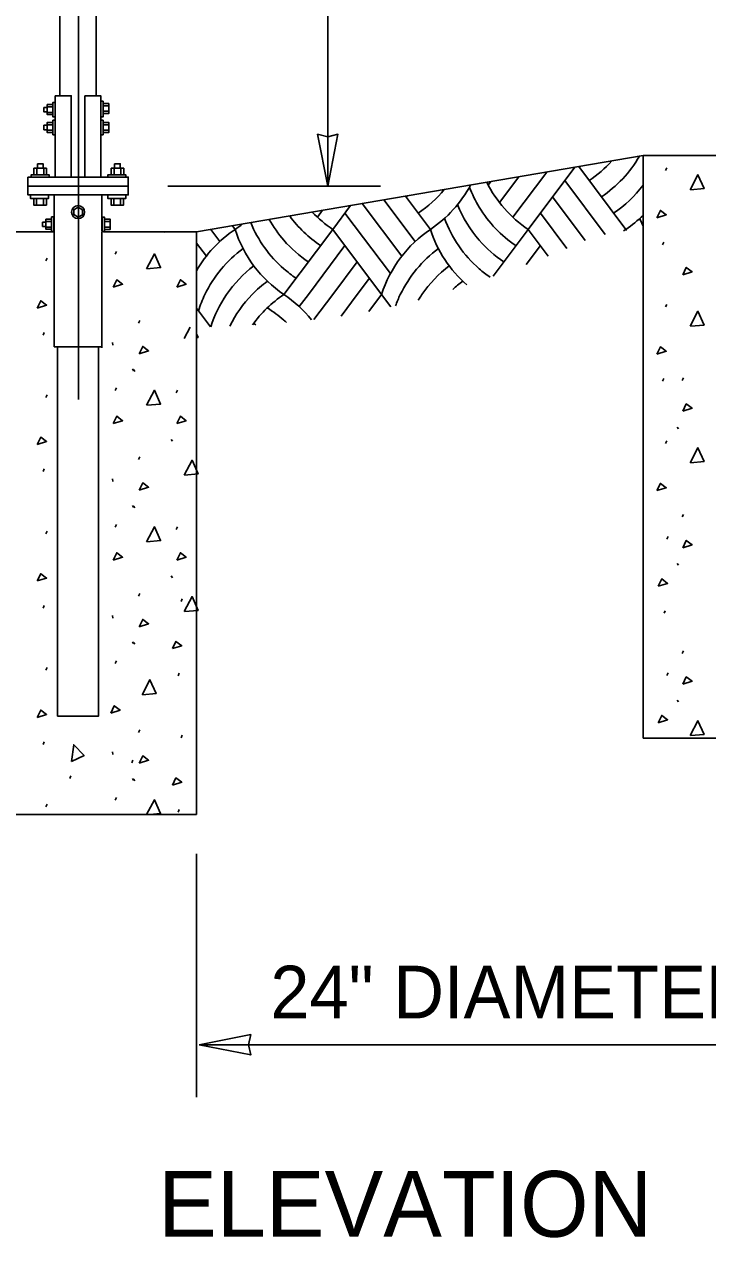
# Model space of a CAD drawing. Extents: x 99862 to 103151, y 99997 to 117076.
# Drawn here: x 101502.3 to 101710.1, y 109727.4 to 110096.3 of the extents above; entities that cross this region are included whole.
import ezdxf

# ---------------------------------------------------------------- set-up
doc = ezdxf.new("R2010")
doc.units = 0
for name, color, linetype in [('Level 15', 7, 'Continuous'), ('Level 2', 7, 'Continuous'), ('Level 20', 7, 'Continuous'), ('Level 5', 7, 'Continuous'), ('Level 6', 7, 'Continuous')]:
    doc.layers.add(name, color=color, linetype=linetype)

msp = doc.modelspace()

# ---------------------------------------------------------------- linework, layer by layer
at = {"layer": 'Level 15'}
for p, q in [((101518.83, 109982.23), (101518.83, 110894.27)), ((101594.55, 110047.07), (101594.55, 110786.06)), ((101610.55, 110047.07), (101545.9, 110047.07)), ((101554.66, 109844.1), (101554.66, 109770.1)), ((101555.43, 109786.1), (101801.61, 109786.1))]:
    msp.add_line(p, q, dxfattribs=at)
for points in [[(101594.55, 110047.07), (101591.46, 110062.8), (101594.55, 110062.07), (101597.63, 110062.8)], [(101555.43, 109786.1), (101571.15, 109783.01), (101570.42, 109786.1), (101571.15, 109789.18)]]:
    msp.add_lwpolyline(points, close=True, dxfattribs=at)
at = {"layer": 'Level 2'}
for p, q in [((101511.38, 110033.49), (101511.38, 110044.36)), ((101525.92, 110033.49), (101525.92, 110044.36)), ((101511.38, 109998.23), (101511.38, 110033.49)), ((101525.92, 110033.17), (101525.92, 109997.91)), ((101525.92, 109998.23), (101511.38, 109998.23))]:
    msp.add_line(p, q, dxfattribs=at)
for points in [[(101513.12, 110074.51), (101513.12, 110394.09), (101524.2, 110394.09), (101524.2, 110074.43)], [(101509.31, 110071.16), (101511.04, 110071.16)], [(101509.31, 110069.46), (101511.04, 110069.46)], [(101528.01, 110071.5), (101526.28, 110071.5)], [(101528.01, 110069.8), (101526.28, 110069.8)], [(101509.31, 110065.73), (101511.04, 110065.73)], [(101528.01, 110065.73), (101526.28, 110065.73)], [(101509.31, 110064.03), (101511.04, 110064.03)], [(101528.01, 110064.03), (101526.28, 110064.03)], [(101506.14, 110052.49), (101506.14, 110050.46)], [(101508.21, 110052.49), (101508.21, 110050.46)], [(101529.63, 110052.49), (101529.63, 110050.46)], [(101531.71, 110052.49), (101531.71, 110050.46)], [(101506.03, 110041.31), (101506.03, 110043.34)], [(101508.11, 110041.31), (101508.11, 110043.34)], [(101529.52, 110041.31), (101529.52, 110043.34)], [(101531.6, 110041.31), (101531.6, 110043.34)], [(101508.9, 110036.32), (101510.63, 110036.32)], [(101528.42, 110036.3), (101526.69, 110036.3)], [(101508.9, 110034.62), (101510.63, 110034.62)], [(101528.42, 110034.6), (101526.69, 110034.6)], [(101524.89, 109998.23), (101524.89, 109885.99), (101512.42, 109885.99), (101512.42, 109998.32)]]:
    msp.add_lwpolyline(points, dxfattribs=at)
for points in [[(101511.73, 110072.51), (101511.73, 110068.1), (101511.04, 110068.1), (101511.04, 110072.51)], [(101511.73, 110074.55), (101516.58, 110074.55), (101516.58, 110049.79), (101511.73, 110049.79)], [(101520.74, 110074.55), (101525.58, 110074.55), (101525.58, 110049.79), (101520.74, 110049.79)], [(101525.58, 110072.85), (101526.28, 110072.85), (101526.28, 110068.1), (101525.58, 110068.1)], [(101508.27, 110070.99), (101509.31, 110070.99), (101509.31, 110069.63), (101508.27, 110069.63)], [(101511.04, 110071.83), (101511.04, 110068.78), (101509.31, 110068.78), (101509.31, 110071.83)], [(101526.28, 110072.17), (101528.01, 110072.17), (101528.01, 110069.12), (101526.28, 110069.12)], [(101508.27, 110065.56), (101509.31, 110065.56), (101509.31, 110064.2), (101508.27, 110064.2)], [(101511.04, 110066.41), (101511.04, 110063.35), (101509.31, 110063.35), (101509.31, 110066.41)], [(101511.73, 110067.09), (101511.73, 110062.68), (101511.04, 110062.68), (101511.04, 110067.09)], [(101525.58, 110067.09), (101526.28, 110067.09), (101526.28, 110062.68), (101525.58, 110062.68)], [(101526.28, 110066.41), (101528.01, 110066.41), (101528.01, 110063.35), (101526.28, 110063.35)], [(101504.37, 110049.78), (101504.37, 110050.46), (101509.91, 110050.46), (101509.91, 110049.78)], [(101505.24, 110050.46), (101505.24, 110052.49), (101509.05, 110052.49), (101509.05, 110050.46)], [(101506.28, 110053.85), (101508.01, 110053.85), (101508.01, 110052.49), (101506.28, 110052.49)], [(101527.69, 110049.78), (101527.69, 110050.46), (101533.23, 110050.46), (101533.23, 110049.78)], [(101528.73, 110050.46), (101528.73, 110052.49), (101532.54, 110052.49), (101532.54, 110050.46)], [(101529.77, 110053.85), (101531.5, 110053.85), (101531.5, 110052.49), (101529.77, 110052.49)], [(101503.42, 110049.79), (101533.9, 110049.79), (101533.9, 110047.07), (101503.42, 110047.07)], [(101503.42, 110047.07), (101533.9, 110047.07), (101533.9, 110044.36), (101503.42, 110044.36)], [(101504.17, 110044.36), (101509.71, 110044.36), (101509.71, 110043.34), (101504.17, 110043.34)], [(101505.21, 110043.34), (101509.02, 110043.34), (101509.02, 110041.31), (101505.21, 110041.31)], [(101527.66, 110044.36), (101533.2, 110044.36), (101533.2, 110043.34), (101527.66, 110043.34)], [(101528.7, 110043.34), (101532.51, 110043.34), (101532.51, 110041.31), (101528.7, 110041.31)], [(101520.01, 110039.88), (101518.72, 110040.64), (101517.41, 110039.9), (101517.4, 110038.4), (101518.69, 110037.64), (101520, 110038.38)], [(101507.86, 110036.15), (101508.9, 110036.15), (101508.9, 110034.79), (101507.86, 110034.79)], [(101510.63, 110037), (101510.63, 110033.95), (101508.9, 110033.95), (101508.9, 110037)], [(101511.32, 110037.68), (101511.32, 110033.27), (101510.63, 110033.27), (101510.63, 110037.68)], [(101526, 110037.66), (101526.69, 110037.66), (101526.69, 110033.25), (101526, 110033.25)], [(101526.69, 110036.98), (101528.42, 110036.98), (101528.42, 110033.92), (101526.69, 110033.92)]]:
    msp.add_lwpolyline(points, close=True, dxfattribs=at)
msp.add_circle((101518.67, 110039.17), 1.98, dxfattribs=at)
at = {"layer": 'Level 5'}
for p, q in [((101554.66, 110033.17), (101690.42, 110056.32)), ((101650.83, 110037.61), (101661.12, 110051.33)), ((101655.49, 110033.92), (101669.63, 110052.78)), ((101670.88, 110052.99), (101685.18, 110033.92)), ((101643.31, 110047.39), (101644.09, 110048.42)), ((101646.75, 110042.08), (101652.6, 110049.87)), ((101666.62, 110048.77), (101678.92, 110032.37)), ((101618.22, 110044.01), (101625.79, 110033.92)), ((101662.91, 110043.82), (101672.84, 110030.58)), ((101591.43, 110037.61), (101593.01, 110039.71)), ((101596.09, 110033.92), (101601.52, 110041.16)), ((101605.05, 110041.77), (101617.06, 110025.76)), ((101611.64, 110042.89), (101621.13, 110030.23)), ((101599.8, 110038.87), (101613.61, 110020.45)), ((101659.2, 110038.87), (101667.27, 110028.1)), ((101558.97, 110033.91), (101561.74, 110030.23)), ((101565.56, 110035.03), (101566.39, 110033.92)), ((101581.24, 110014.12), (101596.09, 110033.92)), ((101596.09, 110033.92), (101610.94, 110014.12)), ((101644.81, 110019.69), (101655.49, 110033.92)), ((101655.49, 110033.92), (101661.6, 110025.77)), ((101554.66, 110029.76), (101557.66, 110025.76)), ((101588.66, 110014.12), (101599.8, 110028.97)), ((101654.88, 110023.21), (101659.2, 110028.97)), ((101596.09, 110014.12), (101603.51, 110024.02)), ((101603.51, 110014.12), (101607.23, 110019.07)), ((101585.89, 110010.43), (101588.66, 110014.12)), ((101590.38, 110006.51), (101596.09, 110014.12)), ((101598.59, 110007.56), (101603.51, 110014.12)), ((101607.08, 110008.98), (101610.94, 110014.12)), ((101610.94, 110014.12), (101613.77, 110010.34)), ((101554.66, 110009.96), (101558.91, 110004.29)), ((101607.23, 110009.17), (101607.34, 110009.02))]:
    msp.add_line(p, q, dxfattribs=at)
for centre, start, end in [((101653.09, 110079.96), 303.9036, 317.7724), ((101656.8, 110075.01), 303.9036, 329.8459), ((101604.83, 110065.11), 303.9036, 331.8449), ((101672.73, 110060.16), 200.8778, 211.332), ((101676.45, 110065.11), 206.713, 236.0964), ((101660.51, 110070.06), 303.9036, 322.7353), ((101597.4, 110075.01), 303.9036, 304.6825), ((101601.11, 110070.06), 303.9036, 320.2298), ((101669.02, 110055.21), 201.4344, 220.9416), ((101672.73, 110060.16), 211.3319, 236.0964), ((101545.43, 110065.11), 303.9036, 308.1444), ((101605.91, 110050.26), 202.3268, 228.9599), ((101609.62, 110055.21), 209.0811, 220.9416), ((101613.34, 110060.16), 216.1301, 236.0964), ((101617.05, 110065.11), 223.6431, 236.0964), ((101665.31, 110050.26), 200.2432, 228.9599), ((101664.22, 110065.11), 303.9036, 314.1913), ((101724.71, 110050.26), 200.2432, 204.1477), ((101578.53, 110016.07), 152.8993, 153.2678), ((101587.35, 110002.73), 123.9036, 150.4555), ((101602.2, 110045.31), 197.6434, 236.0964), ((101646.75, 110002.73), 123.9036, 162.3566), ((101661.6, 110045.31), 197.6434, 228.8095), ((101706.14, 110002.73), 123.9036, 125.2286), ((101720.99, 110045.31), 197.6434, 198.2367), ((101609.62, 110055.21), 220.9415, 236.0964), ((101669.02, 110055.21), 220.9415, 236.0964), ((101591.06, 109997.78), 126.3063, 154.2266), ((101650.46, 109997.78), 126.3063, 154.2266), ((101594.78, 109992.83), 127.1006, 145.4911), ((101605.91, 110050.26), 228.9599, 236.0964), ((101654.17, 109992.83), 127.1006, 145.4911), ((101665.31, 110050.26), 228.9599, 235.28), ((101598.49, 109987.88), 126.331, 135.7128), ((101657.88, 109987.88), 126.331, 132.389), ((101591.06, 109997.78), 154.2265, 162.3566), ((101594.78, 109992.83), 145.491, 162.2427), ((101598.49, 109987.88), 135.7127, 153.7793), ((101602.2, 109982.93), 123.9036, 144.2828), ((101560.28, 109982.93), 38.6821, 56.0963), ((101650.46, 109997.78), 154.2265, 159.9676), ((101654.17, 109992.83), 145.491, 148.6071), ((101556.57, 109977.98), 48.9597, 58.5465), ((101556.57, 109977.98), 47.3973, 48.9597), ((101552.85, 109973.03), 58.0847, 59.3021)]:
    msp.add_arc(centre, 37.58, start, end, dxfattribs=at)
at = {"layer": 'Level 6'}
for p, q in [((101697.25, 110051.8), (101697.61, 110052.6)), ((101554.66, 110033.17), (101526.4, 110033.17)), ((101696.37, 110029.25), (101696.72, 110030.05)), ((101508.91, 110024.34), (101509.27, 110025.14)), ((101529.96, 110026.38), (101530.32, 110027.18)), ((101697.25, 110010.32), (101697.61, 110011.12)), ((101537.07, 110005.43), (101537.42, 110006.23)), ((101508.03, 110001.79), (101508.38, 110002.59)), ((101529.14, 109999.56), (101529.23, 109998.76)), ((101535.2, 109991.49), (101535.56, 109990.95)), ((101535.56, 109991.28), (101535.91, 109990.75)), ((101696.37, 109987.77), (101696.72, 109988.57)), ((101702.3, 109987.97), (101702.66, 109988.77)), ((101529.96, 109984.9), (101530.32, 109985.7)), ((101548.5, 109984.2), (101548.86, 109985)), ((101508.91, 109982.86), (101509.27, 109983.66)), ((101700.79, 109973.82), (101701.15, 109973.29)), ((101547, 109970.05), (101547.35, 109969.52)), ((101697.25, 109968.84), (101697.61, 109969.64)), ((101537.07, 109963.95), (101537.42, 109964.75)), ((101508.03, 109960.31), (101508.38, 109961.1)), ((101529.14, 109958.07), (101529.23, 109957.28)), ((101535.2, 109950), (101535.56, 109949.47)), ((101535.56, 109949.8), (101535.91, 109949.27)), ((101702.3, 109946.49), (101702.66, 109947.28)), ((101529.96, 109943.42), (101530.32, 109944.22)), ((101548.5, 109942.72), (101548.86, 109943.52)), ((101508.91, 109941.38), (101509.27, 109942.18)), ((101697.68, 109939.77), (101698.04, 109940.57)), ((101700.79, 109932.34), (101701.15, 109931.81)), ((101547, 109928.57), (101547.35, 109928.04)), ((101537.07, 109922.46), (101537.42, 109923.26)), ((101549.97, 109920.81), (101550.33, 109921.61)), ((101508.03, 109918.82), (101508.38, 109919.62)), ((101696.8, 109917.22), (101697.15, 109918.01)), ((101529.14, 109916.59), (101529.23, 109915.79)), ((101535.2, 109908.52), (101535.56, 109907.99)), ((101535.56, 109908.32), (101535.91, 109907.79)), ((101702.3, 109905), (101702.66, 109905.8)), ((101508.91, 109899.9), (101509.27, 109900.7)), ((101529.96, 109901.94), (101530.32, 109902.74)), ((101697.68, 109898.29), (101698.04, 109899.09)), ((101549.08, 109898.26), (101549.44, 109899.05)), ((101700.79, 109890.86), (101701.15, 109890.33)), ((101537.07, 109880.98), (101537.42, 109881.78)), ((101508.03, 109877.34), (101508.38, 109878.14)), ((101549.97, 109879.33), (101550.33, 109880.13)), ((101529.14, 109875.11), (101529.23, 109874.31)), ((101534.98, 109871.74), (101535.34, 109872.54)), ((101516.11, 109867.04), (101516.46, 109867.84)), ((101535.2, 109867.04), (101535.56, 109866.51)), ((101535.56, 109866.84), (101535.91, 109866.31)), ((101508.91, 109858.42), (101509.27, 109859.22)), ((101529.96, 109860.46), (101530.32, 109861.26)), ((101549.08, 109856.77), (101549.44, 109857.57))]:
    msp.add_line(p, q, dxfattribs=at)
for points in [[(101719.14, 110056.32), (101690.42, 110056.32), (101690.42, 109879.25)], [(101690.42, 109879.25), (101762.42, 109879.25), (101762.42, 110056.32)], [(101704.7, 110045.97), (101707.1, 110050.49), (101708.96, 110046.32), (101704.79, 110045.97)], [(101694.61, 110037.46), (101695.67, 110039.68), (101697.45, 110038.35), (101694.61, 110037.46)], [(101511.38, 110033.17), (101482.66, 110033.17), (101482.66, 109856.1)], [(101482.66, 109856.1), (101554.66, 109856.1), (101554.66, 110033.17)], [(101539.46, 110021.94), (101541.86, 110026.47), (101543.73, 110022.3), (101539.55, 110021.94)], [(101702.48, 110020.12), (101703.54, 110022.34), (101705.32, 110021.01), (101702.48, 110020.12)], [(101529.34, 110016.35), (101530.4, 110018.57), (101532.18, 110017.24), (101529.34, 110016.35)], [(101548.68, 110016.36), (101549.75, 110018.58), (101551.52, 110017.24), (101548.68, 110016.36)], [(101506.27, 110010), (101507.33, 110012.22), (101509.11, 110010.89), (101506.27, 110010)], [(101704.7, 110004.48), (101707.1, 110009.01), (101708.96, 110004.84), (101704.79, 110004.48)], [(101550.9, 110000.72), (101552.74, 110004.19)], [(101554.66, 110002.2), (101555.16, 110001.07), (101554.66, 110001.03)], [(101537.24, 109996.1), (101538.31, 109998.32), (101540.09, 109996.99), (101537.24, 109996.1)], [(101694.61, 109995.98), (101695.67, 109998.2), (101697.45, 109996.87), (101694.61, 109995.98)], [(101539.46, 109980.46), (101541.86, 109984.99), (101543.73, 109980.82), (101539.55, 109980.46)], [(101702.48, 109978.64), (101703.54, 109980.86), (101705.32, 109979.53), (101702.48, 109978.64)], [(101529.34, 109974.87), (101530.4, 109977.09), (101532.18, 109975.76), (101529.34, 109974.87)], [(101548.68, 109974.87), (101549.75, 109977.09), (101551.52, 109975.76), (101548.68, 109974.87)], [(101506.27, 109968.52), (101507.33, 109970.74), (101509.11, 109969.41), (101506.27, 109968.52)], [(101704.7, 109963), (101707.1, 109967.53), (101708.96, 109963.36), (101704.79, 109963)], [(101550.9, 109959.23), (101553.3, 109963.76), (101555.16, 109959.59), (101550.99, 109959.23)], [(101537.24, 109954.62), (101538.31, 109956.84), (101540.09, 109955.51), (101537.24, 109954.62)], [(101694.61, 109954.5), (101695.67, 109956.72), (101697.45, 109955.39), (101694.61, 109954.5)], [(101539.46, 109938.98), (101541.86, 109943.51), (101543.73, 109939.34), (101539.55, 109938.98)], [(101702.48, 109937.16), (101703.54, 109939.38), (101705.32, 109938.05), (101702.48, 109937.16)], [(101529.34, 109933.39), (101530.4, 109935.61), (101532.18, 109934.28), (101529.34, 109933.39)], [(101548.68, 109933.39), (101549.75, 109935.61), (101551.52, 109934.28), (101548.68, 109933.39)], [(101506.27, 109927.04), (101507.33, 109929.26), (101509.11, 109927.93), (101506.27, 109927.04)], [(101695.04, 109925.43), (101696.1, 109927.65), (101697.88, 109926.32), (101695.04, 109925.43)], [(101550.9, 109917.75), (101553.3, 109922.28), (101555.16, 109918.11), (101550.99, 109917.75)], [(101537.24, 109913.14), (101538.31, 109915.36), (101540.09, 109914.03), (101537.24, 109913.14)], [(101547.32, 109906.47), (101548.39, 109908.69), (101550.17, 109907.36), (101547.32, 109906.47)], [(101538.12, 109892.48), (101540.52, 109897.01), (101542.38, 109892.84), (101538.21, 109892.48)], [(101702.48, 109895.68), (101703.54, 109897.9), (101705.32, 109896.57), (101702.48, 109895.68)], [(101528.58, 109886.91), (101529.64, 109889.13), (101531.42, 109887.8), (101528.58, 109886.91)], [(101506.27, 109885.56), (101507.33, 109887.78), (101509.11, 109886.45), (101506.27, 109885.56)], [(101695.04, 109883.95), (101696.1, 109886.17), (101697.88, 109884.84), (101695.04, 109883.95)], [(101704.7, 109880.04), (101707.1, 109884.57), (101708.96, 109880.39), (101704.79, 109880.04)], [(101516.62, 109872.18), (101517.33, 109877.25), (101520.51, 109873.97), (101516.71, 109872.21)], [(101537.24, 109871.66), (101538.31, 109873.88), (101540.09, 109872.55), (101537.24, 109871.66)], [(101547.32, 109864.99), (101548.39, 109867.21), (101550.17, 109865.88), (101547.32, 109864.99)], [(101539.51, 109856.1), (101541.86, 109860.55), (101543.73, 109856.37), (101540.49, 109856.1)]]:
    msp.add_lwpolyline(points, dxfattribs=at)

# ---------------------------------------------------------------- texts
at = {"layer": 'Level 20'}
for s, height, p in [('24" DIAMETER (TYP.)', 16, (101577.11, 109794.1)), ('ELEVATION', 20, (101543.04, 109727.71))]:
    msp.add_text(s, height=height, dxfattribs=at).set_placement(p)

doc.saveas('drawing.dxf')
